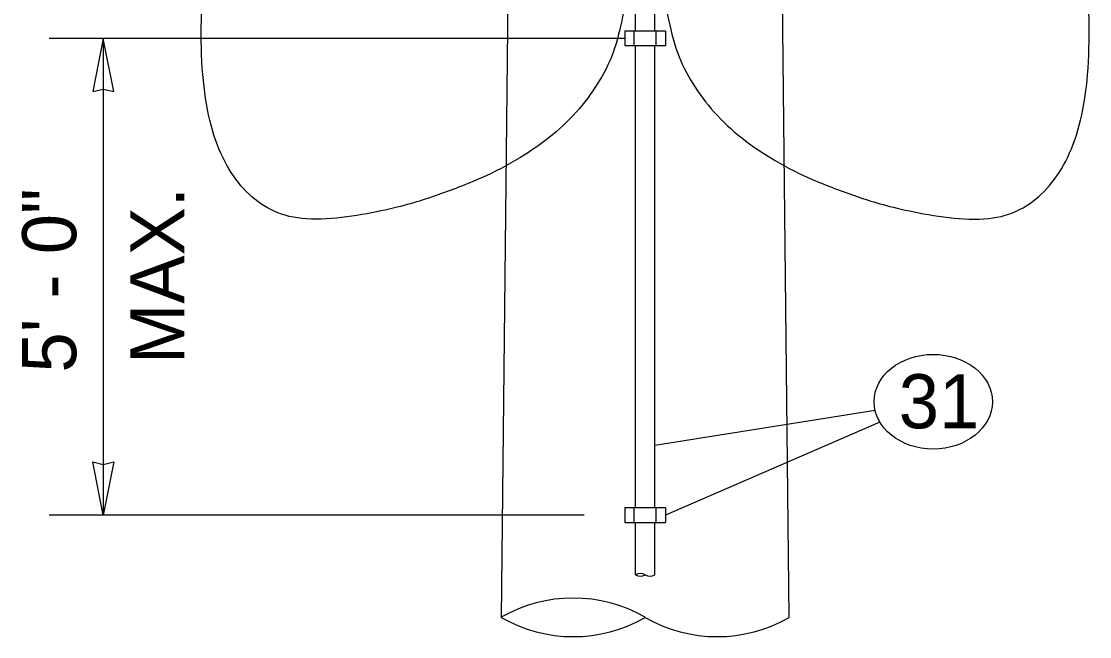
# Model space of a CAD drawing. Extents: x 99862 to 104211, y 98939 to 102076.
# Drawn here: x 101686 to 102002.1, y 101547.8 to 101729.8 of the extents above; entities that cross this region are included whole.
import ezdxf

# ---------------------------------------------------------------- set-up
doc = ezdxf.new("R2010")
doc.units = 0
for name, color, linetype in [('Level 1', 7, 'Continuous'), ('Level 11', 7, 'Continuous'), ('Level 15', 7, 'Continuous'), ('Level 20', 7, 'Continuous'), ('Level 8', 7, 'Continuous')]:
    doc.layers.add(name, color=color, linetype=linetype)

msp = doc.modelspace()

# ---------------------------------------------------------------- linework, layer by layer
at = {"layer": 'Level 1'}
for p, q in [((101831.83, 101908.51), (101827.97, 101553.5)), ((101913.17, 101553.5), (101909.31, 101908.51))]:
    msp.add_line(p, q, dxfattribs=at)
for centre, start, end in [((101849.27, 101516.61), 60, 120), ((101849.27, 101590.39), 240, 300), ((101891.87, 101590.39), 240, 300)]:
    msp.add_arc(centre, 42.6, start, end, dxfattribs=at)
at = {"layer": 'Level 11'}
for points in [[(101859.74, 101772.33), (101884.78, 101693.2), (101689.65, 101651.83), (101790.32, 101936.72)], [(101881.51, 101772.33), (101856.36, 101693.2), (102051.49, 101651.83), (101950.83, 101936.72)]]:
    msp.add_open_spline(points, degree=2, dxfattribs=at)
at = {"layer": 'Level 15'}
for p, q in [((101852.51, 101724.76), (101694.23, 101724.76)), ((101710.23, 101724.76), (101710.23, 101583.74)), ((101864.51, 101724.76), (101852.51, 101724.76)), ((101938.6, 101614.68), (101873.42, 101604.29)), ((101940.04, 101611.19), (101876.63, 101583.74)), ((101852.51, 101583.74), (101694.23, 101583.74))]:
    msp.add_line(p, q, dxfattribs=at)
for points in [[(101710.23, 101724.76), (101707.15, 101709.03), (101710.23, 101709.76), (101713.32, 101709.03)], [(101710.23, 101583.74), (101707.15, 101599.46), (101710.23, 101598.74), (101713.32, 101599.46)]]:
    msp.add_lwpolyline(points, close=True, dxfattribs=at)
at = {"layer": 'Level 20'}
msp.add_ellipse((101955.8, 101617.27), major_axis=(-17.5, 0), ratio=0.8, dxfattribs=at)
at = {"layer": 'Level 8'}
for p, q in [((101867.72, 101726.87), (101867.72, 101772.33)), ((101873.42, 101726.88), (101873.42, 101772.33)), ((101864.51, 101726.9), (101864.51, 101722.62)), ((101876.63, 101726.9), (101864.51, 101726.9)), ((101867.36, 101722.6), (101867.36, 101726.88)), ((101873.78, 101722.6), (101873.78, 101726.88)), ((101876.63, 101726.9), (101876.63, 101722.62)), ((101864.51, 101722.62), (101876.63, 101722.62)), ((101867.72, 101585.88), (101867.72, 101722.59)), ((101873.42, 101585.88), (101873.42, 101722.59)), ((101864.51, 101585.88), (101864.51, 101581.6)), ((101876.63, 101585.88), (101864.51, 101585.88)), ((101867.36, 101581.6), (101867.36, 101585.88)), ((101873.78, 101581.6), (101873.78, 101585.88)), ((101876.63, 101585.88), (101876.63, 101581.6)), ((101864.51, 101581.6), (101876.63, 101581.6)), ((101867.72, 101566.08), (101867.72, 101581.6)), ((101873.42, 101566.08), (101873.42, 101581.6))]:
    msp.add_line(p, q, dxfattribs=at)
for centre, start, end in [((101869.14, 101563.61), 60, 120), ((101869.14, 101568.55), 240, 300), ((101872, 101568.55), 240, 300)]:
    msp.add_arc(centre, 2.85, start, end, dxfattribs=at)

# ---------------------------------------------------------------- texts
at = {"layer": 'Level 20'}
for s, p in [('5\' - 0"', (101702.23, 101625.91)), ('MAX.', (101734.23, 101628.44))]:
    msp.add_text(s, height=16, rotation=90, dxfattribs=at).set_placement(p)
msp.add_text('31', height=16, dxfattribs=at).set_placement((101945.61, 101609.41))

doc.saveas('drawing.dxf')
